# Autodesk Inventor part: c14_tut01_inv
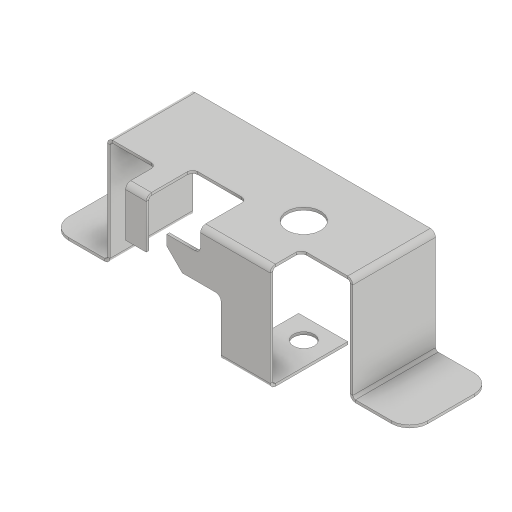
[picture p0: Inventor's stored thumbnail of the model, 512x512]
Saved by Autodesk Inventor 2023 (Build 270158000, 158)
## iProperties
Created: 2015-06
Part Number: c14_tut01_inv
Material: Generic
Document SubType Name: Sheet Metal
Designer: Sandeep
Density: 1 g/cm^3
Sheet Metal Rule: Default_mm
Appearance: Default
Flat Pattern Width: 11.1524 cm
Flat Pattern Length: 21.7129 cm
Flat Pattern Area: 242.15 cm^2
Sheet Metal Width: 111.524 mm
Sheet Metal Length: 217.129 mm
Sheet Metal Area: 24215.030 mm^2
Author: Sandeep
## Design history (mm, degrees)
node "Face1"
  sketch "Sketch1"
    geometry: L1 (0, 12)-(0, 44); L2 (0, 44)-(95, 44); L3 (95, 44)-(95, 12); L4 (95, 12)-(75, 12); L5 (75, 12)-(75, 0); L6 (75, 0)-(48, 0); L7 (48, 0)-(48, 18); L8 (48, 18)-(27, 18); L9 (27, 18)-(27, 0); L10 (27, 0)-(19, 0); L11 (19, 0)-(19, 12); L12 (19, 12)-(0, 12); L13 (0, 0)-(0, 88.508); L14 (0, 0)-(152.255, 0)
    constraints: 28 end point, 11 perpendicular, 4 point on line, 2 vertical, 1 horizontal
    dimensions: "d0" = 26 distance between parallel lines of L2 L8; "d1" = 19 distance between parallel lines of L13 L11; "d2" = 8 distance between parallel lines of L9 L11; "d3" = 32 distance between parallel lines of L12 L2; "d4" = 27 distance between parallel lines of L5 L7; "d5" = 20 distance between parallel lines of L3 L5; "d6" = 95 distance between parallel lines of L1 L3; "d7" = 44 distance between parallel lines of L6 L2
node "Contour Flange1"
node "Contour Flange3"
  sketch "Sketch10"
    geometry: L1 (0, 0)-(41, 0); L2 (41, 0)-(41, 30)
    constraints: 4 end point, 1 horizontal, 1 perpendicular
    dimensions: "d42" = 41 distance of L1.start L1.end; "d43" = 30 distance of L1.end L2.end
sketch "Sketch11"
  geometry: L1 (-3.447, 20)-(8, 20); L2 (8, 20)-(8, -8.777); L3 (8, -8.777)-(-3.447, -8.777); L4 (-3.447, -8.777)-(-3.447, 20); L5 (27, 37)-(27, 0) reference; L6 (0, 39)-(-21, 39) reference; 1 further point
  constraints: 8 end point, 2 parallel, 1 horizontal, 1 perpendicular
  dimensions: "d45" = 19 distance between parallel lines of L5 L2; "d104" = 19 distance between parallel lines of L6 L1
cut "Cut1" sketch "Sketch11" dims "d46" = 1 (= Thickness), "d47" = 0
node "Face2"
  sketch "Sketch12"
    geometry: L1 (0, -17)-(-13, -17); L2 (-13, -17)-(-13, -7); L3 (-13, -7)-(0, -7); L4 (0, 0)-(0, -17) reference; 1 further point
    constraints: 6 end point, 2 perpendicular, 1 horizontal, 1 point on line
    dimensions: "d54" = 13 distance between parallel lines of L2 L4; "d55" = 10 distance of L1.end L2.end
feature "Corner Round1" dims "d56" = 2
feature "Corner Chamfer1" dims "d57" = 6, "d58" = 6, angle "d59" = 45 deg
node "Flange1"
hole "Hole1" diameter "d72" = 13; stored, may be unused: countersink angle "d76" = 90 deg, drill point angle "d78" = 0 deg; dims "d70" = 9, "d71" = 22, "d73" = 6, "d74" = 4, "d75" = 2, "d77" = 1 (= Thickness)
hole "Hole2" diameter "d81" = 8; stored, may be unused: countersink angle "d85" = 90 deg, drill point angle "d87" = 0 deg; dims "d79" = 9, "d80" = 22, "d82" = 6, "d83" = 4, "d84" = 2, "d86" = 1 (= Thickness)
feature "Corner Round2" dims "d88" = 7
workplane "Work Plane1"
node "Contour Flange4"
  sketch "Sketch15"
    geometry: L1 (0, 0.919)-(0, -40.081); L2 (0, -40.081)-(-22, -40.081); 1 further point
    constraints: 4 end point, 1 perpendicular, 1 vertical
    dimensions: "d90" = 41 distance of L1.start L1.end; "d91" = 22 distance of L1.end L2.end
feature "Corner Round4" dims "d101" = 7
feature "Corner Round5" dims "d102" = 2
body "Solid1"
face "Plate1" dims "d103" = 1 (= Thickness)
sketch "Sketch6"
  geometry: L1 (-75, 1)-(20, 1) reference; L2 (20, 1)-(20, -39); L3 (20, -39)-(42, -39); L4 (-75, 1)-(-75, -39); L5 (-75, -39)-(-97, -39); 1 further point
  constraints: 8 end point, 2 perpendicular, 2 vertical
  dimensions: "d9" = 40 distance of L1.end L2.end; "d10" = 22 distance of L2.end L3.end; "d20" = 40 distance of L1.start L4.end
face "Plate2" dims "d11" = 1 (= BendReliefWidth), "d12" = 0.5 (= BendReliefDepth), "d13" = 2 (= MinimumRemnant), "d14" = 1 (= BendRadius), "d15" = 1 (= BendRadius), "d16" = 1, "d17" = 4 (= CornerReliefSize), "d18" = 1 (= GapSize), "d19" = 1 (= JacobiRadiusSize), "d103" = 1 (= Thickness), "SeamGap" = 0.01
bend "Bend1" dims "d11" = 1 (= BendReliefWidth), "d12" = 0.5 (= BendReliefDepth), "d13" = 2 (= MinimumRemnant), "d14" = 1 (= BendRadius), "d15" = 1 (= BendRadius), "d16" = 1, "d103" = 1 (= Thickness), "SeamGap" = 0.01
feature "Corner1" dims "d16" = 1, "d17" = 4 (= CornerReliefSize), "d18" = 1 (= GapSize), "d19" = 1 (= JacobiRadiusSize)
face "Plate4" dims "d33" = 1 (= BendReliefWidth), "d34" = 0.5 (= BendReliefDepth), "d35" = 2 (= MinimumRemnant), "d36" = 1 (= BendRadius), "d37" = 1 (= BendRadius), "d38" = 1, "d39" = 4 (= CornerReliefSize), "d40" = 1 (= GapSize), "d41" = 1 (= JacobiRadiusSize), "d103" = 1 (= Thickness), "SeamGap" = 0.01
bend "Bend3" dims "d33" = 1 (= BendReliefWidth), "d34" = 0.5 (= BendReliefDepth), "d35" = 2 (= MinimumRemnant), "d36" = 1 (= BendRadius), "d37" = 1 (= BendRadius), "d38" = 1, "d103" = 1 (= Thickness), "SeamGap" = 0.01
feature "Corner3" dims "d38" = 1, "d39" = 4 (= CornerReliefSize), "d40" = 1 (= GapSize), "d41" = 1 (= JacobiRadiusSize)
face "Plate5" dims "d49" = 1 (= BendRadius), "d50" = 1 (= BendReliefWidth), "d52" = 2 (= MinimumRemnant), "d103" = 1 (= Thickness)
bend "Bend4" dims "d49" = 1 (= BendRadius), "d50" = 1 (= BendReliefWidth), "d51" = 0.5 (= BendReliefDepth), "d52" = 2 (= MinimumRemnant), "d53" = 1 (= BendRadius), "d103" = 1 (= Thickness), "SeamGap" = 0.01
sketch "Sketch13"
  geometry: L1 (0, 19)-(-8, 19); L2 (-8, 19)-(-8, 0); 1 other entity
  constraints: 4 end point, 4 other
face "Plate6" dims "d60" = 1 (= BendReliefWidth), "d61" = 0.5 (= BendReliefDepth), "d62" = 2 (= MinimumRemnant), "d63" = 1 (= BendRadius), "d64" = 19, "d65" = 90 deg, "d66" = 1 (= BendRadius), "d67" = 4 (= CornerReliefSize), "d68" = 1 (= GapSize), "d69" = 1 (= JacobiRadiusSize), "d103" = 1 (= Thickness), "SeamGap" = 0.01
bend "Bend5" dims "d60" = 1 (= BendReliefWidth), "d61" = 0.5 (= BendReliefDepth), "d62" = 2 (= MinimumRemnant), "d63" = 1 (= BendRadius), "d64" = 19, "d65" = 90 deg, "d66" = 1 (= BendRadius), "d103" = 1 (= Thickness), "SeamGap" = 0.01
feature "Corner4" dims "d64" = 19, "d65" = 90 deg, "d67" = 4 (= CornerReliefSize), "d68" = 1 (= GapSize), "d69" = 1 (= JacobiRadiusSize)
face "Plate7" dims "d92" = 1 (= BendReliefWidth), "d93" = 0.5 (= BendReliefDepth), "d94" = 2 (= MinimumRemnant), "d95" = 1 (= BendRadius), "d96" = 1 (= BendRadius), "d97" = 1, "d98" = 4 (= CornerReliefSize), "d99" = 1 (= GapSize), "d100" = 1 (= JacobiRadiusSize), "d103" = 1 (= Thickness), "SeamGap" = 0.01
bend "Bend6" dims "d92" = 1 (= BendReliefWidth), "d93" = 0.5 (= BendReliefDepth), "d94" = 2 (= MinimumRemnant), "d95" = 1 (= BendRadius), "d96" = 1 (= BendRadius), "d97" = 1, "d103" = 1 (= Thickness), "SeamGap" = 0.01
feature "Corner5" dims "d97" = 1, "d98" = 4 (= CornerReliefSize), "d99" = 1 (= GapSize), "d100" = 1 (= JacobiRadiusSize)
feature "Definition1"
other parameters: "Thickness" = 1 (derived), "BendRadius" = 1 (= Thickness), "BendReliefWidth" = 1 (= Thickness), "BendReliefDepth" = 0.5 (= 0.5 x Thickness), "CornerReliefSize" = 4 (= 4 x Thickness), "MinimumRemnant" = 2 (= 2 x Thickness), "TransitionRadius" = 1 (= BendRadius), "JacobiRadiusSize" = 1 (= BendRadius), "GapSize" = 1 (= Thickness), "d8" = 1 (= BendRadius), "BendRadius" = 1, "BendReliefDepth" = 0.5, "BendReliefWidth" = 1, "CornerReliefSize" = 4, "GapSize" = 1, "JacobiRadiusSize" = 1, "MinimumRemnant" = 2, "Thickness" = 1, "TransitionRadius" = 1
